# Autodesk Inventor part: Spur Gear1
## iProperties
Created: 2008-01
Part Number: Spur Gear1
Material: Steel
Document SubType Name: Modeling
Designer: eruiz-tagle
Mass: 1.54008 g
Surface Area: 2.673 cm^2
Volume: 0.196189 cm^3
Density: 7.85 g/cm^3
CustomPartVersion: 1
Author: eruiz-tagle
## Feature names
1. Extrusion1
